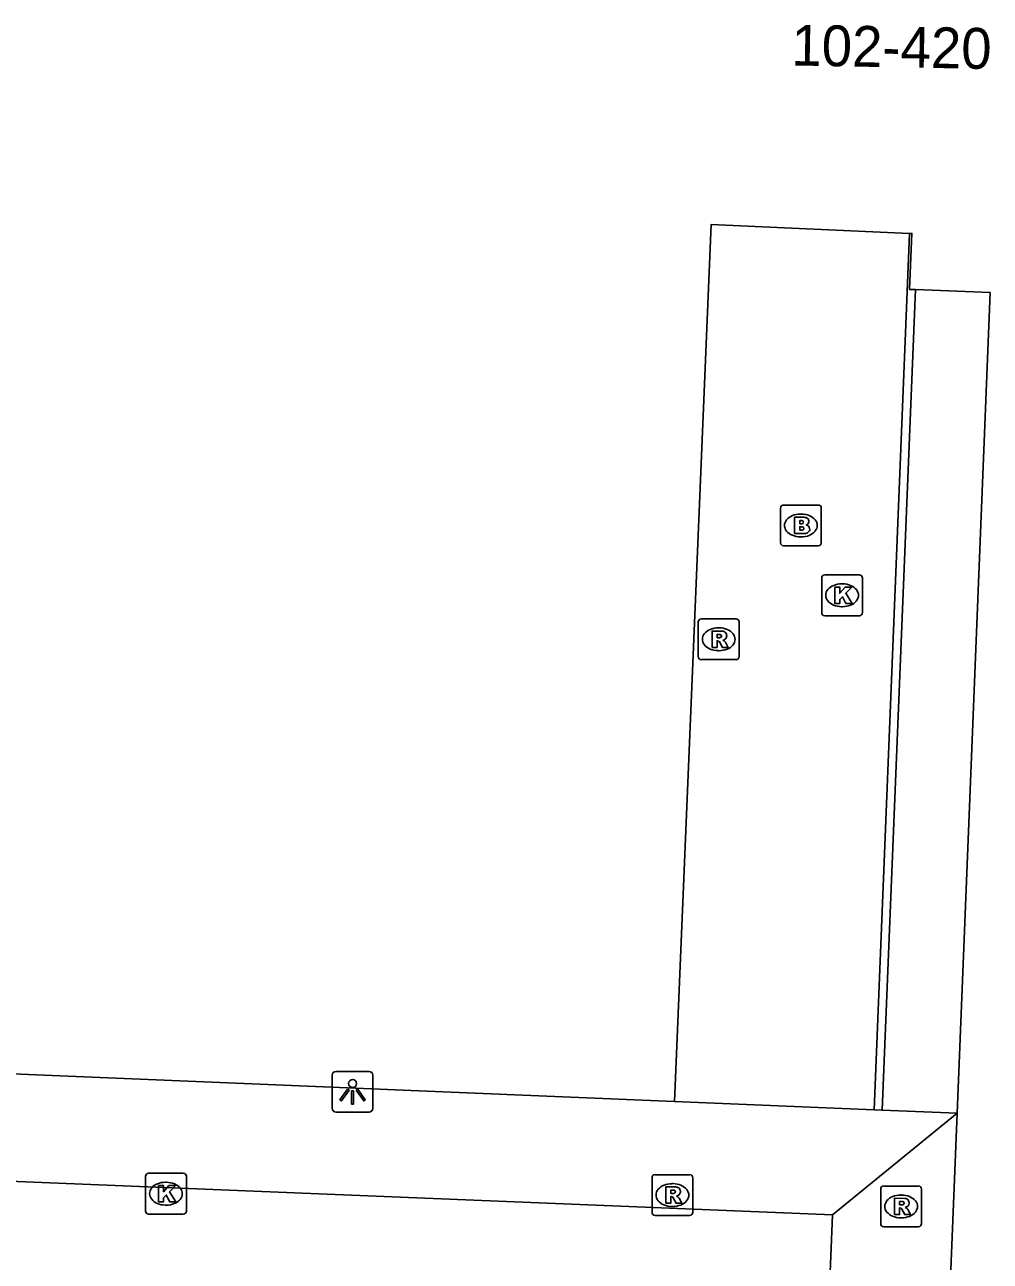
# Model space of a CAD drawing. Extents: x 160891 to 161384, y 386490 to 386907.
# Drawn here: x 161090.69 to 161114.36, y 386660.27 to 386690.57 of the extents above; entities that cross this region are included whole.
import ezdxf

# ---------------------------------------------------------------- set-up
doc = ezdxf.new("R2010")
doc.units = 0
for name, color, linetype in [('IMGEO_Brandkraan', 7, 'Continuous'), ('IMGEO_Kolk', 7, 'Continuous'), ('IMGEO_Lichtpunt', 7, 'Continuous'), ('IMGEO_Pand', 7, 'Continuous'), ('IMGEO_Pand_nummerreeks', 7, 'Continuous'), ('IMGEO_Rijbaan_lokaal_gesloten', 7, 'Continuous'), ('IMGEO_Rijbaan_lokaal_open', 7, 'Continuous'), ('IMGEO_Rioolput', 7, 'Continuous'), ('IMGEO_Voetpad_open', 7, 'Continuous')]:
    doc.layers.add(name, color=color, linetype=linetype)

msp = doc.modelspace()

# ---------------------------------------------------------------- linework, layer by layer
at = {"layer": 'IMGEO_Brandkraan'}
for p, q in [((161109.214, 386677.871), (161109.214, 386678.723)), ((161109.289, 386678.797), (161110.141, 386678.797)), ((161109.702, 386678.577), (161109.727, 386678.577)), ((161110.215, 386678.723), (161110.215, 386677.871)), ((161109.725, 386678.017), (161109.7, 386678.017)), ((161110.141, 386677.797), (161109.289, 386677.797))]:
    msp.add_line(p, q, dxfattribs=at)
for points in [[(161109.214, 386677.871), (161109.214, 386678.723)], [(161109.289, 386678.797), (161110.141, 386678.797)], [(161110.215, 386678.723), (161110.215, 386677.871)], [(161109.562, 386678.497), (161109.562, 386678.097), (161109.775, 386678.097)], [(161109.793, 386678.497), (161109.562, 386678.497)], [(161109.741, 386678.416), (161109.687, 386678.416), (161109.687, 386678.34)], [(161109.687, 386678.34), (161109.74, 386678.34)], [(161109.749, 386678.264), (161109.687, 386678.264), (161109.687, 386678.183)], [(161109.687, 386678.183), (161109.749, 386678.183)], [(161110.141, 386677.797), (161109.289, 386677.797)]]:
    msp.add_lwpolyline(points, dxfattribs=at)
for centre, radius, start, end in [((161109.291, 386678.721), 0.0765, 91.552, 178.448), ((161109.291, 386678.721), 0.0765, 91.552, 178.448), ((161110.139, 386678.721), 0.0765, 1.552, 88.448), ((161110.139, 386678.721), 0.0765, 1.552, 88.448), ((161109.742, 386678.378), 0.0379, 267.8285, 90.9355), ((161109.75, 386678.223), 0.0404, 269.8759, 90.5077), ((161109.797, 386678.352), 0.145, 59.4692, 91.5367), ((161109.822, 386678.399), 0.0922, 285.5137, 58.1501), ((161109.827, 386678.207), 0.105, 301.3115, 78.989), ((161109.781, 386678.348), 0.251, 268.6676, 293.5347), ((161109.291, 386677.873), 0.0765, 181.552, 268.448), ((161109.291, 386677.873), 0.0765, 181.552, 268.448), ((161110.139, 386677.873), 0.0765, 271.552, 358.448), ((161110.139, 386677.873), 0.0765, 271.552, 358.448)]:
    msp.add_arc(centre, radius, start, end, dxfattribs=at)
for centre, major_axis, ratio, start_param, end_param in [((161109.701, 386678.297), (-0.387, 0.002), 0.722429, 4.712389, 7.853982), ((161109.726, 386678.297), (-0.39, 0.002), 0.717154, 1.570796, 4.712389)]:
    msp.add_ellipse(centre, major_axis=major_axis, ratio=ratio, start_param=start_param, end_param=end_param, dxfattribs=at)
at = {"layer": 'IMGEO_Kolk'}
for p, q in [((161110.3, 386677.087), (161111.152, 386677.087)), ((161110.225, 386676.161), (161110.225, 386677.013)), ((161110.713, 386676.867), (161110.738, 386676.867)), ((161111.226, 386677.013), (161111.226, 386676.161)), ((161110.736, 386676.307), (161110.711, 386676.307)), ((161111.152, 386676.087), (161110.3, 386676.087)), ((161093.654, 386661.497), (161093.654, 386662.349)), ((161093.729, 386662.423), (161094.581, 386662.423)), ((161094.142, 386662.203), (161094.167, 386662.203)), ((161094.655, 386662.349), (161094.655, 386661.497)), ((161094.165, 386661.643), (161094.14, 386661.643)), ((161094.581, 386661.423), (161093.729, 386661.423))]:
    msp.add_line(p, q, dxfattribs=at)
for points in [[(161110.3, 386677.087), (161111.152, 386677.087)], [(161110.225, 386676.161), (161110.225, 386677.013)], [(161110.546, 386676.787), (161110.669, 386676.787), (161110.669, 386676.636), (161110.799, 386676.787), (161110.963, 386676.787), (161110.817, 386676.636), (161110.97, 386676.387), (161110.818, 386676.387), (161110.733, 386676.551), (161110.669, 386676.484), (161110.669, 386676.387), (161110.546, 386676.387), (161110.546, 386676.787)], [(161111.226, 386677.013), (161111.226, 386676.161)], [(161111.152, 386676.087), (161110.3, 386676.087)], [(161093.654, 386661.497), (161093.654, 386662.349)], [(161093.729, 386662.423), (161094.581, 386662.423)], [(161094.655, 386662.349), (161094.655, 386661.497)], [(161093.975, 386662.123), (161094.098, 386662.123), (161094.098, 386661.972), (161094.228, 386662.123), (161094.392, 386662.123), (161094.246, 386661.972), (161094.399, 386661.723), (161094.247, 386661.723), (161094.162, 386661.887), (161094.098, 386661.82), (161094.098, 386661.723), (161093.975, 386661.723), (161093.975, 386662.123)], [(161094.581, 386661.423), (161093.729, 386661.423)]]:
    msp.add_lwpolyline(points, dxfattribs=at)
for centre, start, end in [((161110.302, 386677.011), 91.552, 178.448), ((161110.302, 386677.011), 91.552, 178.448), ((161111.15, 386677.011), 1.552, 88.448), ((161111.15, 386677.011), 1.552, 88.448), ((161110.302, 386676.163), 181.552, 268.448), ((161110.302, 386676.163), 181.552, 268.448), ((161111.15, 386676.163), 271.552, 358.448), ((161111.15, 386676.163), 271.552, 358.448), ((161093.731, 386662.347), 91.552, 178.448), ((161093.731, 386662.347), 91.552, 178.448), ((161094.579, 386662.347), 1.552, 88.448), ((161094.579, 386662.347), 1.552, 88.448), ((161093.731, 386661.499), 181.552, 268.448), ((161093.731, 386661.499), 181.552, 268.448), ((161094.579, 386661.499), 271.552, 358.448), ((161094.579, 386661.499), 271.552, 358.448)]:
    msp.add_arc(centre, 0.0765, start, end, dxfattribs=at)
for centre, major_axis, ratio, start_param, end_param in [((161110.712, 386676.587), (-0.387, 0.002), 0.722429, 4.712389, 7.853982), ((161110.737, 386676.587), (-0.39, 0.002), 0.717154, 1.570796, 4.712389), ((161094.141, 386661.923), (-0.387, 0.002), 0.722429, 4.712389, 7.853982), ((161094.166, 386661.923), (-0.39, 0.002), 0.717154, 1.570796, 4.712389)]:
    msp.add_ellipse(centre, major_axis=major_axis, ratio=ratio, start_param=start_param, end_param=end_param, dxfattribs=at)
at = {"layer": 'IMGEO_Lichtpunt'}
for p, q in [((161099.132, 386664.919), (161098.324, 386664.919)), ((161099.132, 386664.919), (161098.324, 386664.919)), ((161098.23, 386664.824), (161098.23, 386664.017)), ((161098.23, 386664.824), (161098.23, 386664.017)), ((161099.226, 386664.017), (161099.226, 386664.824)), ((161099.226, 386664.017), (161099.226, 386664.824)), ((161098.324, 386663.923), (161099.132, 386663.923)), ((161098.324, 386663.923), (161099.132, 386663.923))]:
    msp.add_line(p, q, dxfattribs=at)
for points in [[(161098.604, 386664.488), (161098.643, 386664.46), (161098.455, 386664.198), (161098.417, 386664.225), (161098.604, 386664.488)], [(161098.706, 386664.44), (161098.753, 386664.44), (161098.753, 386664.118), (161098.706, 386664.118), (161098.706, 386664.44)], [(161098.816, 386664.46), (161098.854, 386664.487), (161099.041, 386664.225), (161099.002, 386664.197), (161098.816, 386664.46)]]:
    msp.add_lwpolyline(points, dxfattribs=at)
msp.add_circle((161098.729, 386664.622), 0.0994, dxfattribs=at)
for centre, start, end in [((161098.324, 386664.824), 90, 180), ((161098.324, 386664.824), 90, 180), ((161099.132, 386664.824), 0, 90), ((161099.132, 386664.824), 0, 90), ((161098.324, 386664.017), 180, 270), ((161098.324, 386664.017), 180, 270), ((161099.132, 386664.017), 270, 0), ((161099.132, 386664.017), 270, 360)]:
    msp.add_arc(centre, 0.0946, start, end, dxfattribs=at)
at = {"layer": 'IMGEO_Pand'}
for points in [[(161106.621, 386664.183), (161107.513, 386685.669), (161112.376, 386685.455)], [(161112.376, 386685.455), (161112.436, 386685.452), (161112.38, 386684.082), (161112.521, 386684.076)], [(161112.521, 386684.076), (161114.357, 386684.004), (161113.546, 386663.894)], [(161064.976, 386665.921), (161106.621, 386664.183)], [(161113.546, 386663.894), (161112.853, 386646.718), (161112.621, 386640.934), (161112.559, 386639.396), (161112.378, 386634.915), (161112.255, 386631.87), (161111.098, 386603.328), (161110.606, 386591.176), (161110.319, 386584.108), (161110.116, 386579.09), (161091.136, 386579.854), (161084.022, 386580.14), (161074.316, 386580.531), (161062.171, 386581.019), (161050.874, 386581.474), (161050.87, 386581.374), (161046.888, 386581.503)]]:
    msp.add_lwpolyline(points, dxfattribs=at)
at = {"layer": 'IMGEO_Rijbaan_lokaal_gesloten'}
for points in [[(161112.376, 386685.455), (161111.51, 386663.979)], [(161106.621, 386664.183), (161111.51, 386663.979)]]:
    msp.add_lwpolyline(points, dxfattribs=at)
at = {"layer": 'IMGEO_Rijbaan_lokaal_open'}
for points in [[(161046.865, 386658.1), (161047.155, 386663.993), (161110.493, 386661.403)], [(161107.744, 386593.603), (161110.493, 386661.403)]]:
    msp.add_lwpolyline(points, dxfattribs=at)
at = {"layer": 'IMGEO_Rioolput'}
for p, q in [((161107.201, 386675.083), (161107.201, 386675.935)), ((161107.276, 386676.009), (161108.128, 386676.009)), ((161108.202, 386675.935), (161108.202, 386675.083)), ((161107.689, 386675.789), (161107.714, 386675.789)), ((161107.712, 386675.229), (161107.687, 386675.229)), ((161108.128, 386675.009), (161107.276, 386675.009)), ((161106.067, 386661.463), (161106.067, 386662.315)), ((161106.142, 386662.389), (161106.994, 386662.389)), ((161107.068, 386662.315), (161107.068, 386661.463)), ((161106.555, 386662.169), (161106.58, 386662.169)), ((161111.672, 386661.185), (161111.672, 386662.037)), ((161111.747, 386662.111), (161112.599, 386662.111)), ((161112.16, 386661.891), (161112.185, 386661.891)), ((161112.673, 386662.037), (161112.673, 386661.185)), ((161106.578, 386661.609), (161106.553, 386661.609)), ((161106.994, 386661.389), (161106.142, 386661.389)), ((161112.183, 386661.331), (161112.158, 386661.331)), ((161112.599, 386661.111), (161111.747, 386661.111))]:
    msp.add_line(p, q, dxfattribs=at)
for points in [[(161107.201, 386675.083), (161107.201, 386675.935)], [(161107.276, 386676.009), (161108.128, 386676.009)], [(161108.202, 386675.935), (161108.202, 386675.083)], [(161107.79, 386675.707), (161107.538, 386675.709), (161107.538, 386675.309)], [(161107.716, 386675.628), (161107.662, 386675.628), (161107.662, 386675.547)], [(161107.662, 386675.547), (161107.714, 386675.547)], [(161107.538, 386675.309), (161107.662, 386675.309), (161107.662, 386675.471), (161107.673, 386675.471)], [(161107.72, 386675.442), (161107.791, 386675.309), (161107.931, 386675.309), (161107.866, 386675.435)], [(161108.128, 386675.009), (161107.276, 386675.009)], [(161106.067, 386661.463), (161106.067, 386662.315)], [(161106.142, 386662.389), (161106.994, 386662.389)], [(161107.068, 386662.315), (161107.068, 386661.463)], [(161106.656, 386662.087), (161106.404, 386662.089), (161106.404, 386661.689)], [(161106.582, 386662.008), (161106.528, 386662.008), (161106.528, 386661.927)], [(161106.528, 386661.927), (161106.58, 386661.927)], [(161111.672, 386661.185), (161111.672, 386662.037)], [(161111.747, 386662.111), (161112.599, 386662.111)], [(161112.673, 386662.037), (161112.673, 386661.185)], [(161106.404, 386661.689), (161106.528, 386661.689), (161106.528, 386661.851), (161106.539, 386661.851)], [(161106.586, 386661.822), (161106.657, 386661.689), (161106.797, 386661.689), (161106.732, 386661.815)], [(161112.261, 386661.809), (161112.009, 386661.811), (161112.009, 386661.411)], [(161112.187, 386661.73), (161112.133, 386661.73), (161112.133, 386661.649)], [(161112.133, 386661.649), (161112.185, 386661.649)], [(161106.994, 386661.389), (161106.142, 386661.389)], [(161112.009, 386661.411), (161112.133, 386661.411), (161112.133, 386661.573), (161112.144, 386661.573)], [(161112.191, 386661.544), (161112.262, 386661.411), (161112.402, 386661.411), (161112.337, 386661.537)], [(161112.599, 386661.111), (161111.747, 386661.111)]]:
    msp.add_lwpolyline(points, dxfattribs=at)
for centre, radius, start, end in [((161107.278, 386675.933), 0.0765, 91.552, 178.448), ((161107.278, 386675.933), 0.0765, 91.552, 178.448), ((161108.126, 386675.933), 0.0765, 1.552, 88.448), ((161108.126, 386675.933), 0.0765, 1.552, 88.448), ((161107.698, 386675.736), 0.19, 274.7715, 282.9687), ((161107.722, 386675.532), 0.0964, 77.0061, 93.1865), ((161107.736, 386675.589), 0.0378, 276.6634, 79.6772), ((161107.789, 386675.597), 0.109, 350.3612, 89.416), ((161107.787, 386675.597), 0.112, 277.5842, 350.9817), ((161107.672, 386675.418), 0.0533, 26.0293, 88.6989), ((161107.771, 386675.382), 0.108, 29.5134, 73.7905), ((161107.278, 386675.085), 0.0765, 181.552, 268.448), ((161107.278, 386675.085), 0.0765, 181.552, 268.448), ((161108.126, 386675.085), 0.0765, 271.552, 358.448), ((161108.126, 386675.085), 0.0765, 271.552, 358.448), ((161106.144, 386662.313), 0.0765, 91.552, 178.448), ((161106.144, 386662.313), 0.0765, 91.552, 178.448), ((161106.992, 386662.313), 0.0765, 1.552, 88.448), ((161106.992, 386662.313), 0.0765, 1.552, 88.448), ((161106.564, 386662.116), 0.19, 274.7715, 282.9687), ((161106.588, 386661.912), 0.0964, 77.0061, 93.1865), ((161106.602, 386661.969), 0.0378, 276.6634, 79.6772), ((161106.655, 386661.977), 0.109, 350.3612, 89.416), ((161106.653, 386661.977), 0.112, 277.5842, 350.9817), ((161111.749, 386662.035), 0.0765, 91.552, 178.448), ((161111.749, 386662.035), 0.0765, 91.552, 178.448), ((161112.597, 386662.035), 0.0765, 1.552, 88.448), ((161112.597, 386662.035), 0.0765, 1.552, 88.448), ((161106.538, 386661.798), 0.0533, 26.0293, 88.6989), ((161106.637, 386661.762), 0.108, 29.5134, 73.7905), ((161112.169, 386661.838), 0.19, 274.7715, 282.9687), ((161112.193, 386661.634), 0.0964, 77.0061, 93.1865), ((161112.207, 386661.691), 0.0378, 276.6634, 79.6772), ((161112.26, 386661.699), 0.109, 350.3612, 89.416), ((161112.258, 386661.699), 0.112, 277.5842, 350.9817), ((161112.242, 386661.484), 0.108, 29.5134, 73.7905), ((161106.144, 386661.465), 0.0765, 181.552, 268.448), ((161106.144, 386661.465), 0.0765, 181.552, 268.448), ((161106.992, 386661.465), 0.0765, 271.552, 358.448), ((161106.992, 386661.465), 0.0765, 271.552, 358.448), ((161112.143, 386661.52), 0.0533, 26.0293, 88.6989), ((161111.749, 386661.187), 0.0765, 181.552, 268.448), ((161111.749, 386661.187), 0.0765, 181.552, 268.448), ((161112.597, 386661.187), 0.0765, 271.552, 358.448), ((161112.597, 386661.187), 0.0765, 271.552, 358.448)]:
    msp.add_arc(centre, radius, start, end, dxfattribs=at)
for centre, major_axis, ratio, start_param, end_param in [((161107.688, 386675.509), (-0.387, 0.002), 0.722429, 4.712389, 7.853982), ((161107.713, 386675.509), (-0.39, 0.002), 0.717154, 1.570796, 4.712389), ((161106.554, 386661.889), (-0.387, 0.002), 0.722429, 4.712389, 7.853982), ((161106.579, 386661.889), (-0.39, 0.002), 0.717154, 1.570796, 4.712389), ((161112.159, 386661.611), (-0.387, 0.002), 0.722429, 4.712389, 7.853982), ((161112.184, 386661.611), (-0.39, 0.002), 0.717154, 1.570796, 4.712389)]:
    msp.add_ellipse(centre, major_axis=major_axis, ratio=ratio, start_param=start_param, end_param=end_param, dxfattribs=at)
at = {"layer": 'IMGEO_Voetpad_open'}
for points in [[(161111.71, 386663.971), (161112.521, 386684.076)], [(161110.493, 386661.403), (161113.546, 386663.894)], [(161111.51, 386663.979), (161111.71, 386663.971)], [(161111.71, 386663.971), (161113.546, 386663.894)]]:
    msp.add_lwpolyline(points, dxfattribs=at)

# ---------------------------------------------------------------- texts
at = {"layer": 'IMGEO_Pand_nummerreeks'}
msp.add_text('102-420', height=1, rotation=358.9744, dxfattribs=at).set_placement((161109.475, 386689.57))

doc.saveas('drawing.dxf')
